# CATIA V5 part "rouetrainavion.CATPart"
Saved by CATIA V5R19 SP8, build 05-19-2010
Part number: rouetrainavion
Bounding box of the stored display mesh (mm): x 0 to 140, y -75 to 75, z -75 to 75
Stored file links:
  C:\Users\rcousturie\Desktop\EU_thinkMotion\iao\IAO_MMS_Groupe1\flamrini\Lamrini_projet_IAO2011\Lamrini_projet_IAO2011\projet_iao_traindatterrissage\projet_iao_traindatterrissage\rouetrainavion.CATPart
  C:\Users\rcousturie\Desktop\EU_thinkMotion\iao\IAO_MMS_Groupe1\flamrini\Lamrini_projet_IAO2011\Lamrini_projet_IAO2011\projet_iao_traindatterrissage\projet_iao_traindatterrissage\trainavion.CATProduct
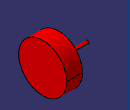
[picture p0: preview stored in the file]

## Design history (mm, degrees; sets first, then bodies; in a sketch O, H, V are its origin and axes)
Set1
  Sketch1 on yz-plane, origin (0, 0, 0), H (0, 1, 0), V (0, 0, 1)
    circle A1 centre (0, 0) radius 5
    point P1 (0, 0)
    reference projected point E1 (0, 0) from Point1
    radius A1 = 5
    coincidence: P1 E1
Set2
  Point1: linked copy from another document
Body1 (main body)
  Pad1: profile Sketch1, direction (1, 0, 0), length 90
  Sketch2 on end face of Pad1, origin (90, 0, 0), H (0, 1, 0), V (0, 0, 1)
    circle A1 centre (0, 0) radius 75
    point P1 (0, 0)
    reference projected point E1 (0, 0) from Point1
    radius A1 = 75
    coincidence: P1 E1
  Pad2: profile Sketch2, direction (1, 0, 0), length 50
